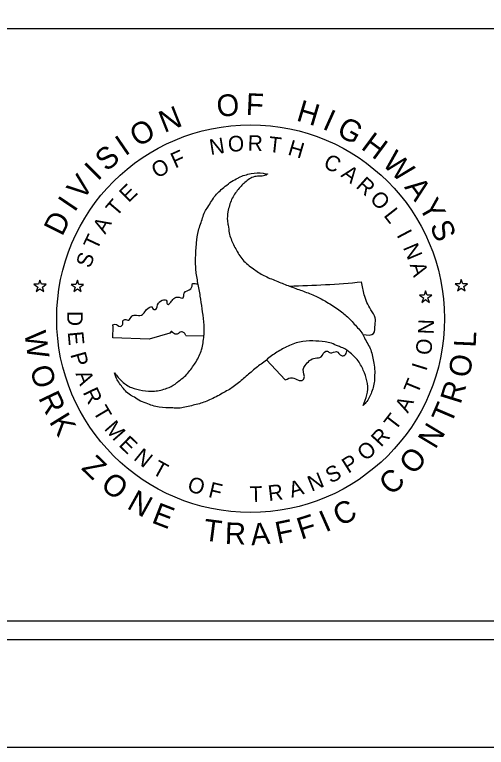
# Model space of a CAD drawing. Extents: x 2157572 to 5059327, y 715220 to 1674494.
# Drawn here: x 2168053 to 2168928, y 722289 to 723649 of the extents above; entities that cross this region are included whole.
import ezdxf

# ---------------------------------------------------------------- set-up
doc = ezdxf.new("R2010")
doc.units = 0
for name, color, linetype in [('Exist Road Primary US Structure Standard Bridge Number Label', 7, 'Continuous'), ('Exist Road Secondary Type 51 Divided Label', 7, 'Continuous'), ('Exist Road Secondary Type 51 Undivided 3 Lane Attributed', 7, 'Continuous'), ('Map Preparation County North Arrow CELL', 7, 'Continuous'), ('Map Preparation County North Arrow White Shapes', 7, 'Continuous')]:
    doc.layers.add(name, color=color, linetype=linetype)

msp = doc.modelspace()

# ---------------------------------------------------------------- linework, layer by layer
at = {"layer": 'Exist Road Primary US Structure Standard Bridge Number Label'}
msp.add_circle((2168490.7, 723084.4), 359.8, dxfattribs=at)
at = {"layer": 'Exist Road Secondary Type 51 Divided Label'}
msp.add_lwpolyline([(2157571.9, 722288.7), (2171075.9, 722288.7), (2171075.9, 731088.6), (2157571.9, 731088.6)], close=True, dxfattribs=at)
at = {"layer": 'Exist Road Secondary Type 51 Undivided 3 Lane Attributed'}
msp.add_lwpolyline([(2170485.5, 727897.1), (2170495.8, 729042.7), (2158875.9, 729042.7), (2158875.9, 722488.7), (2166434.4, 722488.7), (2166434.4, 723622.8), (2170875.9, 723622.8), (2170875.9, 727897.1)], close=True, dxfattribs=at)
at = {"layer": 'Map Preparation County North Arrow CELL'}
for p, q in [((2168088.5, 723148.1), (2168095.6, 723143)), ((2168097.2, 723148.1), (2168088.5, 723148.1)), ((2168099.8, 723156.1), (2168097.2, 723148.1)), ((2168102.6, 723148.1), (2168099.8, 723156.1)), ((2168111.3, 723148.1), (2168102.6, 723148.1)), ((2168104.3, 723143), (2168111.3, 723148.1)), ((2168104.3, 723143), (2168111.3, 723148.1)), ((2168166.6, 723148), (2168158, 723148)), ((2168158, 723148), (2168165, 723142.9)), ((2168169.2, 723156), (2168166.6, 723148)), ((2168172.1, 723148), (2168169.2, 723156)), ((2168180.7, 723148), (2168172.1, 723148)), ((2168173.7, 723142.9), (2168180.7, 723148)), ((2168879, 723149.2), (2168870.3, 723149.2)), ((2168870.3, 723149.2), (2168877.4, 723144.1)), ((2168881.5, 723157.2), (2168879, 723149.2)), ((2168884.4, 723149.2), (2168881.5, 723157.2)), ((2168893.1, 723149.2), (2168884.4, 723149.2)), ((2168886.1, 723144.1), (2168893.1, 723149.2)), ((2168095.6, 723143), (2168093, 723134.6)), ((2168093, 723134.6), (2168099.8, 723139.8)), ((2168099.8, 723139.8), (2168106.9, 723134.6)), ((2168099.8, 723139.8), (2168106.8, 723134.6)), ((2168106.9, 723134.6), (2168104.3, 723143)), ((2168106.8, 723134.6), (2168104.3, 723143)), ((2168165, 723142.9), (2168162.5, 723134.5)), ((2168162.5, 723134.5), (2168169.2, 723139.6)), ((2168169.2, 723139.6), (2168176.2, 723134.5)), ((2168176.2, 723134.5), (2168173.7, 723142.9)), ((2168815.3, 723136.1), (2168812.8, 723128.1)), ((2168818.2, 723128.1), (2168815.3, 723136.1)), ((2168877.4, 723144.1), (2168874.8, 723135.7)), ((2168874.8, 723135.7), (2168881.5, 723140.9)), ((2168881.5, 723140.9), (2168888.6, 723135.7)), ((2168888.6, 723135.7), (2168886.1, 723144.1)), ((2168812.8, 723128.1), (2168804.1, 723128.1)), ((2168804.1, 723128.1), (2168811.2, 723122.9)), ((2168811.2, 723122.9), (2168808.6, 723114.6)), ((2168826.9, 723128.1), (2168818.2, 723128.1)), ((2168819.8, 723122.9), (2168826.9, 723128.1)), ((2168822.4, 723114.6), (2168819.8, 723122.9)), ((2168808.6, 723114.6), (2168815.3, 723119.7)), ((2168815.3, 723119.7), (2168822.4, 723114.6)), ((2168235.1, 723048.5), (2168235.8, 723069.8)), ((2168340.7, 723057.4), (2168302.3, 723046)), ((2168370.3, 723052.9), (2168404, 723052.6)), ((2168302.3, 723046), (2168235.1, 723048.5)), ((2168520.3, 723007.9), (2168554.8, 722970.6))]:
    msp.add_line(p, q, dxfattribs=at)
for start, end in [(265.6785, 265.9762), (271.2035, 275.3236)]:
    msp.add_arc((2168523.4, 725010), 1865.5, start, end, dxfattribs=at)
for points in [[(2168238.4, 722983.7), (2168252.4, 722967.6), (2168269.8, 722956.4), (2168289.8, 722951.2), (2168312.3, 722949.9), (2168335.3, 722955.3), (2168350.5, 722963), (2168357, 722968.2), (2168368.1, 722977), (2168376.1, 722985.6), (2168389.4, 723004.5), (2168399.7, 723026.8), (2168404, 723052.4), (2168404.2, 723054.5), (2168404, 723078.6), (2168400.8, 723102.8), (2168397.3, 723126.3), (2168393, 723150.5), (2168389.2, 723174.6), (2168388.7, 723198), (2168390.3, 723224.8), (2168394.1, 723247.8), (2168401.6, 723271.4), (2168405.7, 723282.6), (2168411.3, 723291.6), (2168425.3, 723312.9), (2168443.5, 723330), (2168455.5, 723339.1), (2168466.9, 723345.1), (2168468.9, 723346.2), (2168491.6, 723353.5), (2168514, 723354.3), (2168521.5, 723352.4)], [(2168522.1, 723353), (2168521.5, 723352.4), (2168500.9, 723348.5), (2168482.2, 723338.9), (2168467.8, 723324.3), (2168455.5, 723305.6), (2168448.7, 723282.8), (2168447.6, 723265.8), (2168449.1, 723257.7), (2168451, 723243.5), (2168454.3, 723232.3), (2168464.4, 723211.5), (2168478.3, 723191.3), (2168498.5, 723174.8), (2168500.2, 723173.5), (2168520.8, 723161.7), (2168543.8, 723152.2), (2168565.7, 723143.6), (2168588.7, 723135.3), (2168611.4, 723126.3), (2168632.1, 723115.1), (2168654.6, 723100.5), (2168672.4, 723085.7), (2168689.2, 723067.4), (2168696.9, 723058.2), (2168701.9, 723048.7), (2168713.5, 723026.2), (2168719, 723001.7), (2168721, 722986.7), (2168720.6, 722973.8), (2168720.6, 722971.6), (2168715.2, 722948.2), (2168704.7, 722928.5), (2168699.5, 722923.1)], [(2168235.8, 723069.8), (2168235.1, 723071.8), (2168238.8, 723074.1), (2168248.7, 723070), (2168253.7, 723074.3), (2168253.4, 723078.6), (2168257.5, 723082.9), (2168264.3, 723081.5), (2168270.4, 723089.2), (2168276, 723090.8), (2168288, 723090.8), (2168302.3, 723105.1), (2168308.1, 723106), (2168309.7, 723102.1), (2168313.3, 723101.4), (2168319.7, 723113.2), (2168321.2, 723114.8), (2168332.1, 723119.3), (2168335, 723117), (2168335.9, 723111.8), (2168337.5, 723110.9), (2168341.1, 723113.4), (2168346.1, 723119.8), (2168355.2, 723124.5), (2168365.6, 723123.1), (2168367.4, 723131.7), (2168379.6, 723139.9), (2168382.1, 723144.8), (2168382.7, 723149.8)], [(2168698.9, 723054.7), (2168718.7, 723057.1), (2168721.6, 723072.7), (2168721.8, 723085.8), (2168713.7, 723101), (2168701.5, 723128.8), (2168696.5, 723152.5)], [(2168370.3, 723052.9), (2168367.6, 723058), (2168362.2, 723059.6), (2168354.7, 723055.8), (2168349.3, 723056), (2168343.2, 723060.5), (2168340.7, 723057.4)], [(2168699.5, 722923.1), (2168706.4, 722942.8), (2168707.5, 722963.7), (2168701.9, 722983.7), (2168691.8, 723003.6), (2168675.7, 723020.8), (2168661.5, 723030.2), (2168653.5, 723033.1), (2168640.7, 723038.6), (2168628.8, 723041.2), (2168606.1, 723043.1), (2168581.4, 723041), (2168557.1, 723031.8), (2168555.2, 723030.9), (2168534.6, 723018.7), (2168515, 723003.8), (2168496.3, 722989.2), (2168477.7, 722973.3), (2168458.5, 722957.9), (2168438.6, 722945.8), (2168414.5, 722933.6), (2168392.8, 722925.7), (2168368.8, 722920.3), (2168356.8, 722918.2), (2168346.2, 722918.6), (2168321.1, 722919.9), (2168296.8, 722927.2), (2168283.1, 722933), (2168272.2, 722940.1), (2168270.2, 722941.1), (2168252.6, 722957.2), (2168240.8, 722976.1), (2168238.4, 722983.7)], [(2168554.8, 722970.6), (2168568.3, 722974.6), (2168579.6, 722970.3), (2168585.1, 722969.4), (2168589.6, 722972.8), (2168588.2, 722989.8), (2168592.1, 722997.7), (2168610.4, 723011.3), (2168621.7, 723013.7), (2168630.1, 723024.1), (2168633.4, 723023.9), (2168638.6, 723021), (2168650.2, 723023.2), (2168659.4, 723015.8), (2168664.9, 723016.2), (2168669.2, 723024.7)]]:
    msp.add_spline(points, degree=3, dxfattribs=at)
at = {"layer": 'Map Preparation County North Arrow White Shapes'}
for points in [[(2170875.9, 730888.7), (2158875.9, 730888.7), (2158875.9, 722488.7), (2170875.9, 722488.7)], [(2168034.7, 723622.8), (2168946.7, 723622.8), (2168946.7, 722522.8), (2168034.7, 722522.8)]]:
    msp.add_lwpolyline(points, close=True, dxfattribs=at)

# ---------------------------------------------------------------- texts
at = {"layer": 'Exist Road Primary US Structure Standard Bridge Number Label'}
for s, height, rotation, p in [('T', 29, 353.7884, (2168522.7, 723394.1)), ('W', 40.3, 278.15, (2168070.6, 723058.8)), ('L', 40.3, 87.429, (2168908.2, 723030.3)), ('O', 40.3, 78.9896, (2168896.3, 722973)), ('O', 40.3, 287.1147, (2168080.4, 722991.5)), ('R', 40.3, 72.7519, (2168880.1, 722924.1)), ('R', 40.3, 295.5541, (2168096, 722937.5)), ('T', 40.3, 66.881, (2168862.3, 722886.4)), ('K', 40.3, 301.7918, (2168115.8, 722893.1)), ('N', 40.3, 58.892, (2168833.4, 722840.5)), ('O', 40.3, 50.4526, (2168793.8, 722792.7)), ('Z', 40.3, 316.1688, (2168175.2, 722805.8)), ('O', 40.3, 322.5233, (2168210.1, 722771)), ('C', 40.3, 43.0807, (2168752, 722754.5)), ('N', 40.3, 330.9626, (2168259.3, 722733.1)), ('E', 40.3, 338.9517, (2168305.1, 722706.4)), ('C', 40.3, 28.0033, (2168657.1, 722697.9)), ('I', 40.3, 23.7503, (2168629.6, 722687.3)), ('T', 40.3, 352.6948, (2168401.5, 722673)), ('F', 40.3, 17.7627, (2168584.4, 722674)), ('R', 40.3, 358.5656, (2168442.6, 722666)), ('A', 40.3, 4.8034, (2168492.2, 722663.6)), ('F', 40.3, 11.7751, (2168541, 722666.4))]:
    msp.add_text(s, height=height, rotation=rotation, dxfattribs=at).set_placement(p)
at = {"layer": 'Map Preparation County North Arrow CELL'}
for s, height, rotation, p in [('O', 40.3, 5.7649, (2168429.6, 723458.4)), ('F', 40.3, 357.2575, (2168481.2, 723462.9)), ('H', 40.3, 343.454, (2168573.8, 723452.5)), ('N', 40.3, 21.5861, (2168330.4, 723428.8)), ('I', 40.3, 335.804, (2168622.2, 723437.4)), ('O', 40.3, 30.0935, (2168281.4, 723401.9)), ('G', 40.3, 331.5167, (2168648, 723426.3)), ('I', 40.3, 34.3808, (2168257.7, 723385.2)), ('N', 29, 9.0227, (2168416.5, 723387.9)), ('O', 29, 3.9446, (2168449.5, 723393.7)), ('R', 29, 358.8665, (2168485.1, 723396)), ('H', 40.3, 323.4632, (2168693.7, 723400.6)), ('H', 29, 343.6322, (2168558.1, 723389.1)), ('S', 40.3, 40.5848, (2168223.7, 723356.1)), ('F', 29, 24.2569, (2168350.7, 723362.8)), ('W', 40.3, 315.8133, (2168733, 723370.9)), ('C', 29, 333.4761, (2168623.7, 723366)), ('I', 40.3, 44.8722, (2168207.1, 723338.5)), ('O', 29, 29.335, (2168316.9, 723343.9)), ('A', 29, 323.3199, (2168656.7, 723349)), ('V', 40.3, 51.5806, (2168178.3, 723302.6)), ('R', 29, 318.2418, (2168684.6, 723328.7)), ('A', 40.3, 306.7762, (2168774.9, 723328.3)), ('E', 29, 44.5692, (2168264.3, 723298.5)), ('I', 40.3, 55.8679, (2168164.1, 723280.6)), ('O', 29, 313.1637, (2168710.3, 723305.4)), ('Y', 40.3, 299.7484, (2168801.4, 723292.8)), ('T', 29, 49.6473, (2168241.6, 723272.1)), ('L', 29, 308.0856, (2168736.4, 723275.7)), ('D', 40.3, 63.459, (2168141, 723235.7)), ('A', 29, 59.8035, (2168220.9, 723239.9)), ('S', 40.3, 293.2249, (2168822.4, 723256.8)), ('I', 29, 297.9295, (2168760.8, 723239.8)), ('T', 29, 64.8816, (2168205.6, 723209.9)), ('N', 29, 292.8514, (2168772.9, 723216.6)), ('S', 29, 69.9597, (2168192.9, 723176.5)), ('A', 29, 287.7733, (2168785.6, 723184.4)), ('D', 29, 270.272, (2168150.3, 723098.5)), ('N', 29, 87.733, (2168830.2, 723054.8)), ('E', 29, 275.3501, (2168151.2, 723059.6)), ('O', 29, 82.9269, (2168825.1, 723015.6)), ('P', 29, 285.5063, (2168155.9, 723018.1)), ('I', 29, 72.7707, (2168816.5, 722985.9)), ('A', 29, 290.5843, (2168165.4, 722982.4)), ('T', 29, 67.6926, (2168800.5, 722942.8)), ('R', 29, 295.6624, (2168178.7, 722947.8)), ('A', 29, 62.6145, (2168782.5, 722907.8)), ('T', 29, 300.7405, (2168197.2, 722912.1)), ('T', 29, 52.4584, (2168759, 722875)), ('M', 29, 310.8967, (2168217.8, 722879.6)), ('R', 29, 47.3803, (2168732.6, 722844.7)), ('E', 29, 315.9748, (2168244.6, 722848.9)), ('O', 29, 42.3022, (2168704.4, 722818.7)), ('N', 29, 321.0529, (2168272, 722823.6)), ('T', 29, 331.209, (2168306, 722797.5)), ('P', 29, 32.146, (2168671.8, 722796.2)), ('S', 29, 27.068, (2168638.9, 722777.9)), ('N', 29, 21.9899, (2168603.6, 722763)), ('O', 29, 341.3652, (2168371.3, 722765.5)), ('F', 29, 346.4433, (2168410.8, 722753.6)), ('A', 29, 16.9118, (2168566.8, 722751.8)), ('T', 29, 1.6775, (2168489.2, 722743.9)), ('R', 29, 6.7556, (2168524.5, 722745.7))]:
    msp.add_text(s, height=height, rotation=rotation, dxfattribs=at).set_placement(p)

doc.saveas('drawing.dxf')
